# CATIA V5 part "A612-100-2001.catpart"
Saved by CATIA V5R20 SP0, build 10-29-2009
Part number: A612-100-2001
Source: Unknown
Property "A": "30.000"
Property "ARTICLENO": "A612-100-2001"
Property "B": "40.000"
Property "BOMINFO": "A612-100-2001"
Property "CODE": "A612-100-2001"
Property "D": "22.000"
Property "FORM": "A"
Property "L": "200.000"
Property "L1": "45.000"
Property "L2": "110.000"
Property "L3": "0.000"
Property "LINA": "A612-100-2001"
Property "NB": "A612-100-2001"
Property "NBSYN": "$CODE."
Property "NN": "A612"
Property "NT": "CDI 3357 E-Type Wear Plates, steel and self-lubricating"
Property "SUPPLIER": "CF"
Property "T": "30.000"
Property "W": "100.000"
Bounding box of the stored display mesh (mm): x 0 to 30, y 0 to 200, z 0 to 100
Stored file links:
  C:\Users\Utente\Desktop\3D files A612\A612-100-2001.catpart
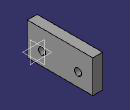
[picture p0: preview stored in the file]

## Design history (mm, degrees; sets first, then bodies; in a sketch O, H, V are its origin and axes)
Body1 "Geometry.1" (main body)
  Solid1 "A612-100-2001.catpart": solid without history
